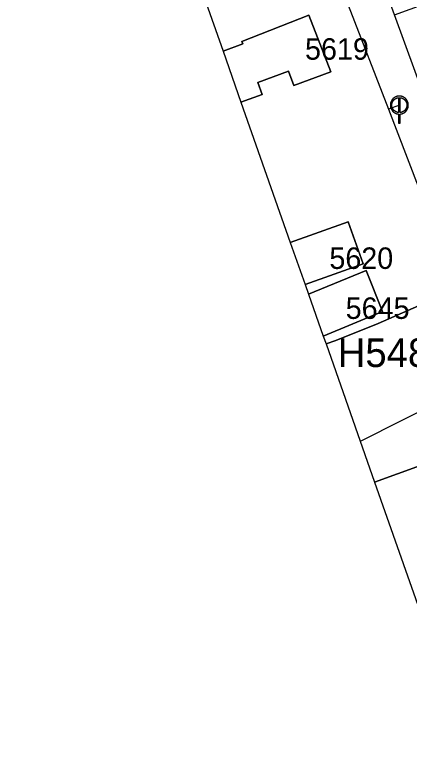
# Model space of a CAD drawing. Extents: x -562248 to -562040, y -1079385 to -1079027.
# Drawn here: x -562151.9 to -562124.4, y -1079242.8 to -1079190.5 of the extents above; entities that cross this region are included whole.
import ezdxf

# ---------------------------------------------------------------- set-up
doc = ezdxf.new("R2010")
doc.units = 0
for name, color, linetype in [('Default', 7, 'Continuous'), ('Kanalizační přípojka', 7, 'Continuous'), ('Kanalizační stoka', 7, 'Continuous'), ('Kanalizační šachta', 7, 'Continuous'), ('Označení hydrantu', 7, 'Continuous'), ('Parcela-polygon', 7, 'Continuous'), ('Parcela-text', 7, 'Continuous'), ('Vodovodní řad', 7, 'Continuous')]:
    doc.layers.add(name, color=color, linetype=linetype)

msp = doc.modelspace()

# ---------------------------------------------------------------- linework, layer by layer
at = {"layer": 'Default'}
for points in [[(-562125.388, -1079196.266), (-562125.487, -1079196.319), (-562125.565, -1079196.396), (-562125.621, -1079196.496)], [(-562125.08, -1079196.185), (-562125.186, -1079196.185), (-562125.288, -1079196.212), (-562125.388, -1079196.266)], [(-562124.772, -1079196.266), (-562124.872, -1079196.212), (-562124.974, -1079196.185), (-562125.08, -1079196.185)], [(-562124.539, -1079196.496), (-562124.595, -1079196.396), (-562124.673, -1079196.319), (-562124.772, -1079196.266)], [(-562125.621, -1079196.496), (-562125.677, -1079196.596), (-562125.705, -1079196.701), (-562125.705, -1079196.81)], [(-562125.6, -1079196.81), (-562125.6, -1079196.719), (-562125.577, -1079196.632), (-562125.53, -1079196.549)], [(-562125.53, -1079196.549), (-562125.484, -1079196.466), (-562125.419, -1079196.401), (-562125.336, -1079196.356)], [(-562125.336, -1079196.356), (-562125.265, -1079196.318), (-562125.196, -1079196.296), (-562125.131, -1079196.29)], [(-562125.029, -1079196.29), (-562124.962, -1079196.296), (-562124.894, -1079196.318), (-562124.824, -1079196.356)], [(-562124.824, -1079196.356), (-562124.741, -1079196.401), (-562124.676, -1079196.466), (-562124.628, -1079196.549)], [(-562124.628, -1079196.549), (-562124.581, -1079196.632), (-562124.558, -1079196.719), (-562124.558, -1079196.81)], [(-562124.455, -1079196.81), (-562124.455, -1079196.701), (-562124.483, -1079196.596), (-562124.539, -1079196.496)], [(-562125.705, -1079196.81), (-562125.705, -1079196.917), (-562125.677, -1079197.021), (-562125.622, -1079197.12)], [(-562125.622, -1079197.12), (-562125.567, -1079197.219), (-562125.489, -1079197.297), (-562125.39, -1079197.352)], [(-562125.532, -1079197.068), (-562125.577, -1079196.985), (-562125.6, -1079196.9), (-562125.6, -1079196.81)], [(-562125.339, -1079197.259), (-562125.422, -1079197.214), (-562125.486, -1079197.15), (-562125.532, -1079197.068)], [(-562125.131, -1079197.328), (-562125.2, -1079197.323), (-562125.269, -1079197.3), (-562125.339, -1079197.259)], [(-562124.819, -1079197.259), (-562124.89, -1079197.3), (-562124.96, -1079197.323), (-562125.029, -1079197.328)], [(-562124.626, -1079197.068), (-562124.671, -1079197.15), (-562124.736, -1079197.214), (-562124.819, -1079197.259)], [(-562124.767, -1079197.352), (-562124.668, -1079197.297), (-562124.591, -1079197.219), (-562124.537, -1079197.12)], [(-562124.558, -1079196.81), (-562124.558, -1079196.9), (-562124.58, -1079196.985), (-562124.626, -1079197.068)], [(-562124.537, -1079197.12), (-562124.482, -1079197.021), (-562124.455, -1079196.917), (-562124.455, -1079196.81)], [(-562125.39, -1079197.352), (-562125.304, -1079197.401), (-562125.218, -1079197.428), (-562125.131, -1079197.433)], [(-562125.029, -1079197.433), (-562124.942, -1079197.428), (-562124.855, -1079197.401), (-562124.767, -1079197.352)]]:
    msp.add_open_spline(points, degree=2, dxfattribs=at)
at = {"layer": 'Kanalizační přípojka'}
msp.add_lwpolyline([(-562125.08, -1079196.81), (-562125.839, -1079197.104)], dxfattribs=at)
at = {"layer": 'Kanalizační stoka'}
msp.add_lwpolyline([(-562141.01, -1079157.91), (-562139.044, -1079162.99), (-562138.57, -1079164.22), (-562134.691, -1079175.12), (-562133.092, -1079178.37), (-562131.481, -1079182.534), (-562125.84, -1079197.1), (-562123.1, -1079204.19)], dxfattribs=at)
at = {"layer": 'Kanalizační šachta'}
for points in [[(-562125.131, -1079196.29), (-562125.131, -1079197.328)], [(-562125.029, -1079197.328), (-562125.029, -1079196.29)], [(-562125.131, -1079198.06), (-562125.029, -1079198.06), (-562125.029, -1079197.433)], [(-562125.131, -1079197.433), (-562125.131, -1079198.06)]]:
    msp.add_lwpolyline(points, dxfattribs=at)
at = {"layer": 'Parcela-polygon'}
for p, q in [((-562151.942, -1079151.733), (-562137.401, -1079193.038)), ((-562137.401, -1079193.038), (-562136.147, -1079196.602)), ((-562136.147, -1079196.602), (-562132.7, -1079206.393)), ((-562132.7, -1079206.393), (-562131.664, -1079209.335)), ((-562131.664, -1079209.335), (-562131.427, -1079210.008)), ((-562131.427, -1079210.008), (-562130.395, -1079212.939)), ((-562130.395, -1079212.939), (-562130.204, -1079213.482)), ((-562130.204, -1079213.482), (-562126.807, -1079223.131))]:
    msp.add_line(p, q, dxfattribs=at)
for points in [[(-562130.204, -1079213.482), (-562129.52, -1079213.24), (-562126.56, -1079212.06), (-562110.18, -1079204.89), (-562109.412, -1079204.67), (-562108.694, -1079204.319), (-562108.049, -1079203.848), (-562107.496, -1079203.271), (-562107.054, -1079202.606), (-562106.734, -1079201.874), (-562106.547, -1079201.097), (-562106.5, -1079200.3), (-562107.01, -1079197.84), (-562112.9, -1079182.58), (-562117.83, -1079168.5), (-562124.14, -1079150.14), (-562125.7, -1079148.16), (-562127.71, -1079147.6), (-562130.14, -1079147.9), (-562151.942, -1079151.733)], [(-562121.43, -1079173.64), (-562121.29, -1079173.59), (-562116.34, -1079187.19), (-562111.38, -1079200.8), (-562120.46, -1079204.1), (-562125.42, -1079190.5), (-562130.38, -1079176.88), (-562121.43, -1079173.64)], [(-562136.147, -1079196.602), (-562134.67, -1079196.07), (-562134.96, -1079195.22), (-562132.83, -1079194.45), (-562132.46, -1079195.45), (-562129.86, -1079194.48), (-562131.41, -1079190.53), (-562136.08, -1079192.36), (-562136.02, -1079192.52), (-562137.401, -1079193.038)], [(-562137.401, -1079193.038), (-562136.02, -1079192.52), (-562136.08, -1079192.36), (-562131.41, -1079190.53), (-562129.86, -1079194.48), (-562132.46, -1079195.45), (-562132.83, -1079194.45), (-562134.96, -1079195.22), (-562134.67, -1079196.07), (-562136.147, -1079196.602)], [(-562131.664, -1079209.335), (-562127.61, -1079207.9), (-562128.65, -1079204.96), (-562132.7, -1079206.393)], [(-562132.7, -1079206.393), (-562128.65, -1079204.96), (-562127.61, -1079207.9), (-562131.664, -1079209.335)], [(-562110.18, -1079204.89), (-562126.56, -1079212.06), (-562129.52, -1079213.24), (-562130.204, -1079213.482)], [(-562130.395, -1079212.939), (-562126.25, -1079211.22), (-562127.39, -1079208.36), (-562131.427, -1079210.008)], [(-562131.427, -1079210.008), (-562127.39, -1079208.36), (-562126.25, -1079211.22), (-562130.395, -1079212.939)], [(-562125.839, -1079250.062), (-562115.46, -1079274.84), (-562111.34, -1079272.6), (-562115.82, -1079264.13), (-562111.86, -1079261.96), (-562112.48, -1079260.84), (-562109.81, -1079259.38), (-562109.2, -1079260.5), (-562101.14, -1079256.08), (-562102.73, -1079253.17), (-562100.18, -1079251.98), (-562102.28, -1079247.51), (-562108.03, -1079234.16), (-562113.76, -1079220.84), (-562114.87, -1079218.31), (-562116.77, -1079219.12), (-562123.59, -1079221.97), (-562126.807, -1079223.131)], [(-562126.807, -1079223.131), (-562123.59, -1079221.97)], [(-562126.807, -1079223.131), (-562118.618, -1079246.395), (-562125.839, -1079250.062)]]:
    msp.add_lwpolyline(points, dxfattribs=at)
msp.add_lwpolyline([(-562116.34, -1079187.19), (-562111.38, -1079200.8), (-562120.46, -1079204.1), (-562125.42, -1079190.5)], close=True, dxfattribs=at)
at = {"layer": 'Vodovodní řad'}
msp.add_lwpolyline([(-562127.816, -1079220.267), (-562127.696, -1079220.234), (-562119.47, -1079216.08)], dxfattribs=at)

# ---------------------------------------------------------------- texts
at = {"layer": 'Označení hydrantu'}
msp.add_text('H548', height=2, dxfattribs=at).set_placement((-562129.387, -1079215.103))
at = {"layer": 'Parcela-text'}
for s, p in [('5619', (-562131.67, -1079193.64)), ('5620', (-562129.97, -1079208.25)), ('5645', (-562128.83, -1079211.74))]:
    msp.add_text(s, height=1.5, dxfattribs=at).set_placement(p)

doc.saveas('drawing.dxf')
